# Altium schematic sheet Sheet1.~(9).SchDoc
size A4
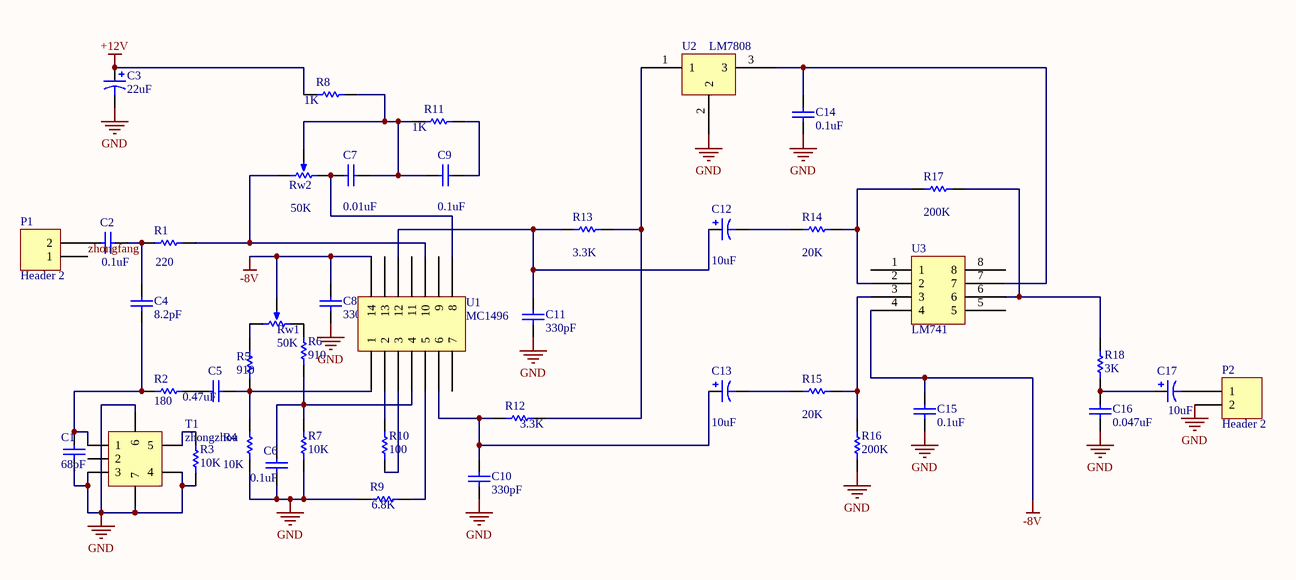
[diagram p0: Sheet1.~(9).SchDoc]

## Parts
C1  value 68pF  [2012[0805]]  (hidden comment: Cap)
C2  value 0.1uF  [2012[0805]]  (hidden comment: Cap)
C3  value 22uF  [C1206]  (hidden comment: Cap Pol1)
C4  value 8.2pF  [2012[0805]]  (hidden comment: Cap)
C5  value 0.47uF  [2012[0805]]  (hidden comment: Cap)
C6  value 0.1uF  [2012[0805]]  (hidden comment: Cap)
C7  value 0.01uF  [2012[0805]]  (hidden comment: Cap)
C8  value 330pF  [2012[0805]]  (hidden comment: Cap)
C9  value 0.1uF  [2012[0805]]  (hidden comment: Cap)
C10  value 330pF  [2012[0805]]  (hidden comment: Cap)
C11  value 330pF  [2012[0805]]  (hidden comment: Cap)
C12  value 10uF  [C1206]  (hidden comment: Cap Pol1)
C13  value 10uF  [C1206]  (hidden comment: Cap Pol1)
C14  value 0.1uF  [2012[0805]]  (hidden comment: Cap)
C15  value 0.1uF  [2012[0805]]  (hidden comment: Cap)
C16  value 0.047uF  [2012[0805]]  (hidden comment: Cap)
C17  value 10uF  [C1206]  (hidden comment: Cap Pol1)
P1  Header 2  [HDR1X2]
P2  Header 2  [HDR1X2]
R1  value 220  [2012[0805]]  (hidden comment: Res1)
R2  value 180  [2012[0805]]  (hidden comment: Res1)
R3  value 10K  [2012[0805]]  (hidden comment: Res1)
R4  value 10K  [2012[0805]]  (hidden comment: Res1)
R5  value 910  [2012[0805]]  (hidden comment: Res1)
R6  value 910  [2012[0805]]  (hidden comment: Res1)
R7  value 10K  [2012[0805]]  (hidden comment: Res1)
R8  value 1K  [2012[0805]]  (hidden comment: Res1)
R9  value 6.8K  [2012[0805]]  (hidden comment: Res1)
R10  value 100  [2012[0805]]  (hidden comment: Res1)
R11  value 1K  [2012[0805]]  (hidden comment: Res1)
R12  value 3.3K  [2012[0805]]  (hidden comment: Res1)
R13  value 3.3K  [2012[0805]]  (hidden comment: Res1)
R14  value 20K  [2012[0805]]  (hidden comment: Res1)
R15  value 20K  [2012[0805]]  (hidden comment: Res1)
R16  value 200K  [2012[0805]]  (hidden comment: Res1)
R17  value 200K  [2012[0805]]  (hidden comment: Res1)
R18  value 3K  [2012[0805]]  (hidden comment: Res1)
Rw1  value 50K  [VR5]  (hidden comment: RPot)
Rw2  value 50K  [VR5]  (hidden comment: RPot)
T1  zhongzhou  [zhongzhou]
U1  MC1496  [MC1496]
U2  LM7808  [LM7808]
U3  LM741  [LM741]

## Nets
+12V: C3.1 R8.1
-8V: C8.2 C15.2 Rw1.3(TAP) U1.14 U3.4
GND: C1.1 C3.2 C6.1 C8.1 C10.1 C11.1 C14.1 C15.1 C16.1 P2.2 R3.1 R4.1 R7.1 R9.1 R16.1 T1.3 T1.4 T1.6 T1.7 U2.2
zhongfang: P1.1
NetC1_2: C1.2 C4.1 R2.1 T1.1
NetC2_1: C2.1 P1.2
NetC2_2: C2.2 C4.2 R1.1
NetC5_1: C5.1 R2.2
NetC5_2: C5.2 R4.2 R5.1 U1.1
NetC6_2: C6.2 R6.1 R7.2 U1.4
NetC7_1: C7.1 Rw2.1(TOP) U1.8
NetC7_2: C7.2 C9.1 R8.2 R11.1 Rw2.3(TAP)
NetC9_2: C9.2 R11.2
NetC10_2: C10.2 C13.1 R12.1 U1.6
NetC11_2: C11.2 C12.1 R13.1 U1.12
NetC12_2: C12.2 R14.1
NetC13_2: C13.2 R15.1
NetC14_2: C14.2 U2.3 U3.7
NetC16_2: C16.2 C17.1 R18.1
NetC17_2: C17.2 P2.1
NetR1_2: R1.2 Rw2.2(BOT) U1.10
NetR3_2: R3.2 T1.5
NetR5_2: R5.2 Rw1.2(BOT)
NetR6_2: R6.2 Rw1.1(TOP)
NetR9_2: R9.2 U1.5
NetR10_1: R10.1 U1.3
NetR10_2: R10.2 U1.2
NetR12_2: R12.2 R13.2 U2.1
NetR14_2: R14.2 R17.1 U3.2
NetR15_2: R15.2 R16.2 U3.3
NetR17_2: R17.2 R18.2 U3.6

Not connected (* = marked no-connect by the designer): T1 2; U1 7 9 11 13; U3 1 5 8

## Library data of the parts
C1 C2 C4-C11 C14-C16 = Cap: Capacitor
C3 C12 C13 C17 = Cap Pol1: Polarized Capacitor (Radial)
P1 P2 = Header 2: Header, 2-Pin
R1-R18 = Res1: Resistor
Rw1 Rw2 = RPot: Potentiometer; Sim Note: Enter the Resistance value and the set point into parameter fields.; Set Position: 0.5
